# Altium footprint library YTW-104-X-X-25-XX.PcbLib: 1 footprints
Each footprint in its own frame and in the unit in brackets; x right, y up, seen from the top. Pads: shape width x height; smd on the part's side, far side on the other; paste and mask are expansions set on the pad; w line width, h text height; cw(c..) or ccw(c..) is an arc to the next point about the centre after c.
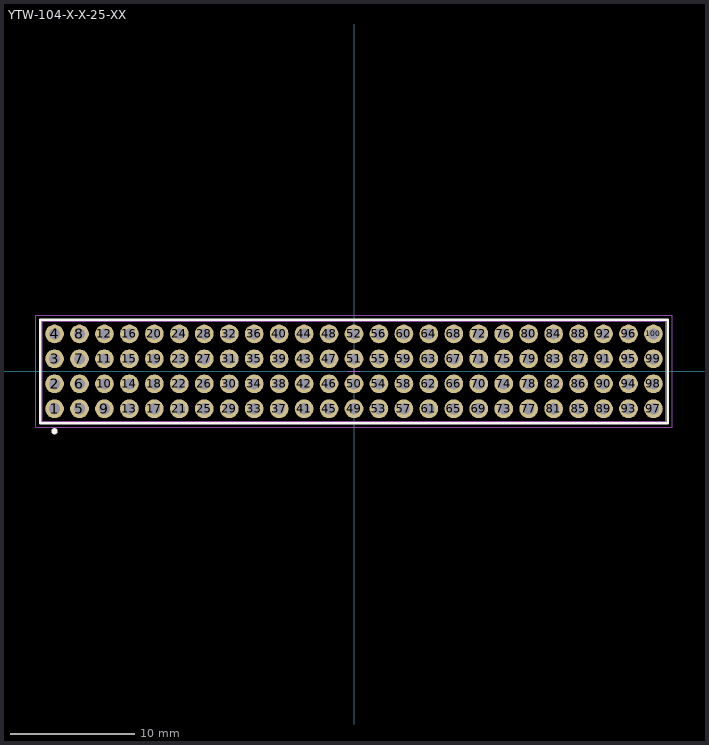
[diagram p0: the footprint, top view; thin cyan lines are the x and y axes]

## YTW-104-X-X-25-XX [mm] "2.00mm pitch, 100 pin, stacker; 4 rows"
height 3.05
pads (100):
  round 1.5 hole 0.89 mask+0: 1(-24,-3) 2(-24,-1) 3(-24,1) 4(-24,3) 5(-22,-3) 6(-22,-1) 7(-22,1) 8(-22,3) 9(-20,-3) 10(-20,-1) 11(-20,1) 12(-20,3) 13(-18,-3) 14(-18,-1) 15(-18,1) 16(-18,3) 17(-16,-3) 18(-16,-1) 19(-16,1) 20(-16,3) 21(-14,-3) 22(-14,-1) 23(-14,1) 24(-14,3) 25(-12,-3) 26(-12,-1) 27(-12,1) 28(-12,3) 29(-10,-3) 30(-10,-1) 31(-10,1) 32(-10,3) 33(-8,-3) 34(-8,-1) 35(-8,1) 36(-8,3) 37(-6,-3) 38(-6,-1) 39(-6,1) 40(-6,3) 41(-4,-3) 42(-4,-1) 43(-4,1) 44(-4,3) 45(-2,-3) 46(-2,-1) 47(-2,1) 48(-2,3) 49(0,-3) 50(0,-1) 51(0,1) 52(0,3) 53(2,-3) 54(2,-1) 55(2,1) 56(2,3) 57(4,-3) 58(4,-1) 59(4,1) 60(4,3) 61(6,-3) 62(6,-1) 63(6,1) 64(6,3) 65(8,-3) 66(8,-1) 67(8,1) 68(8,3) 69(10,-3) 70(10,-1) 71(10,1) 72(10,3) 73(12,-3) 74(12,-1) 75(12,1) 76(12,3) 77(14,-3) 78(14,-1) 79(14,1) 80(14,3) 81(16,-3) 82(16,-1) 83(16,1) 84(16,3) 85(18,-3) 86(18,-1) 87(18,1) 88(18,3) 89(20,-3) 90(20,-1) 91(20,1) 92(20,3) 93(22,-3) 94(22,-1) 95(22,1) 96(22,3) 97(24,-3) 98(24,-1) 99(24,1) 100(24,3)
Top Overlay:
  circle w0.25: c-24,-4.8 r0.125
  lines w0.2: -25.15,-4.15 25.15,-4.15 25.15,4.15 -25.15,4.15 -25.15,-4.15
Mechanical 12:
  lines w0.001: -25,-4 25,-4 25,4 -25,4 -25,-4
Mechanical 13:
  lines w0.1: -25,-4 25,-4 25,4 -25,4 -25,-4
  text ".Designator" at 0,0 h1.52
Mechanical 15:
  lines w0.05: -24.5,-3 -23.5,-3 ; -24,-3.5 -24,-2.5 ; -0.5,0 0.5,0 ; 0,-0.5 0,0.5 ; -25.5,-4.5 25.5,-4.5 25.5,4.5 -25.5,4.5 -25.5,-4.5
